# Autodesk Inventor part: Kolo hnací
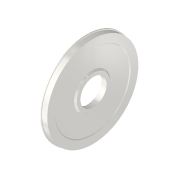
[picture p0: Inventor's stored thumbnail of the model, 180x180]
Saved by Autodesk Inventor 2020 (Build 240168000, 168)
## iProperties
Created: 2025-03
Part Number: Kolo hnací
Material: Ocel
Document SubType Name: Modeling
Designer: doma
Density: 7.85 g/cm^3
Appearance: Ocel
Mass: 5823.41 g
Surface Area: 1260.06 cm^2
Volume: 741.836 cm^3
Author: doma
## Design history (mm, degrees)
sketch "Náčrt1"
  geometry: L1 (-2, 130)-(-2, 132.5); L2 (-2, 132.5)-(-5, 132.5); L3 (-5, 37.5)-(15, 37.5); L4 (15, 130)-(-2, 130); L5 (15, 130)-(15, 110); L6 (15, 110)-(11, 110); L7 (11, 110)-(11, 106); L8 (11, 106)-(15, 110); L9 (11, 106)-(11, 51.5); L10 (11, 51.5)-(11, 47.5); L11 (11, 47.5)-(15, 47.5); L12 (15, 47.5)-(11, 51.5); L13 (15, 47.5)-(15, 37.5); L14 (5, 37.5)-(5, 28.239); L15 (-1, 106)-(-1, 51.5); L16 (-5, 47.5)-(-1, 51.5); L17 (-1, 106)-(-5, 110); L18 (-5, 132.5)-(-5, 110); L19 (-5, 47.5)-(-5, 37.5); L20 (-28.012, 0)-(19.413, 0); L21 (15, 42.5)-(10, 42.5); L22 (10, 42.5)-(10, 37.5); L23 (-5, 42.5)-(0, 42.5); L24 (0, 42.5)-(0, 37.5); 3 further points
  constraints: 48 end point, 9 perpendicular, 7 symmetric about line, 5 vertical, 2 horizontal, 2 midpoint, 2 point on line
  dimensions: "d0" = 2.5 distance of L1.start L1.end; "d1" = 3 distance of L1.end L2.end; "d2" = 20 distance of L3.start L3.end; "d3" = 20 distance of L4.start L5.end; "d4" = 4 distance of L5.end L6.end; "d5" = 4 distance of L6.end L7.end; "d6" = 4 distance of L9.end L10.end; "d7" = 4 distance of L10.end L11.end; "d8" = 130 distance from line of point (0, 0) L4; "d11" = 47.5 vertical distance of point (0, 0) L11.end; "d12" = 37.5 distance from line of point (0, 0) L3; "d26" = 5 distance of L21.start L21.end; "d28" = 42.5 distance from line of point (0, 0) L21
revolve "Rotace1" sketch "Náčrt1" stored, may be unused: angle "d13" = 120 deg
chamfer "Zkosení2" distance "d33" = 1; stored, may be unused: second distance "d34" = 2, angle "d35" = 45 deg
fillet "Zaoblení1" dims "d36" = 0.2
sketch "Náčrt3"
  geometry: C1 r 154.856 at (0, 0); C2 r 81.113 at (0, 0); 1 further point
  constraints: 2 centre point, 2 coincident
extrude "Vysunutí1" cut sketch "Náčrt3" distance "d37" = 2; taper "d38" = 0 deg
node "Těleso1"
